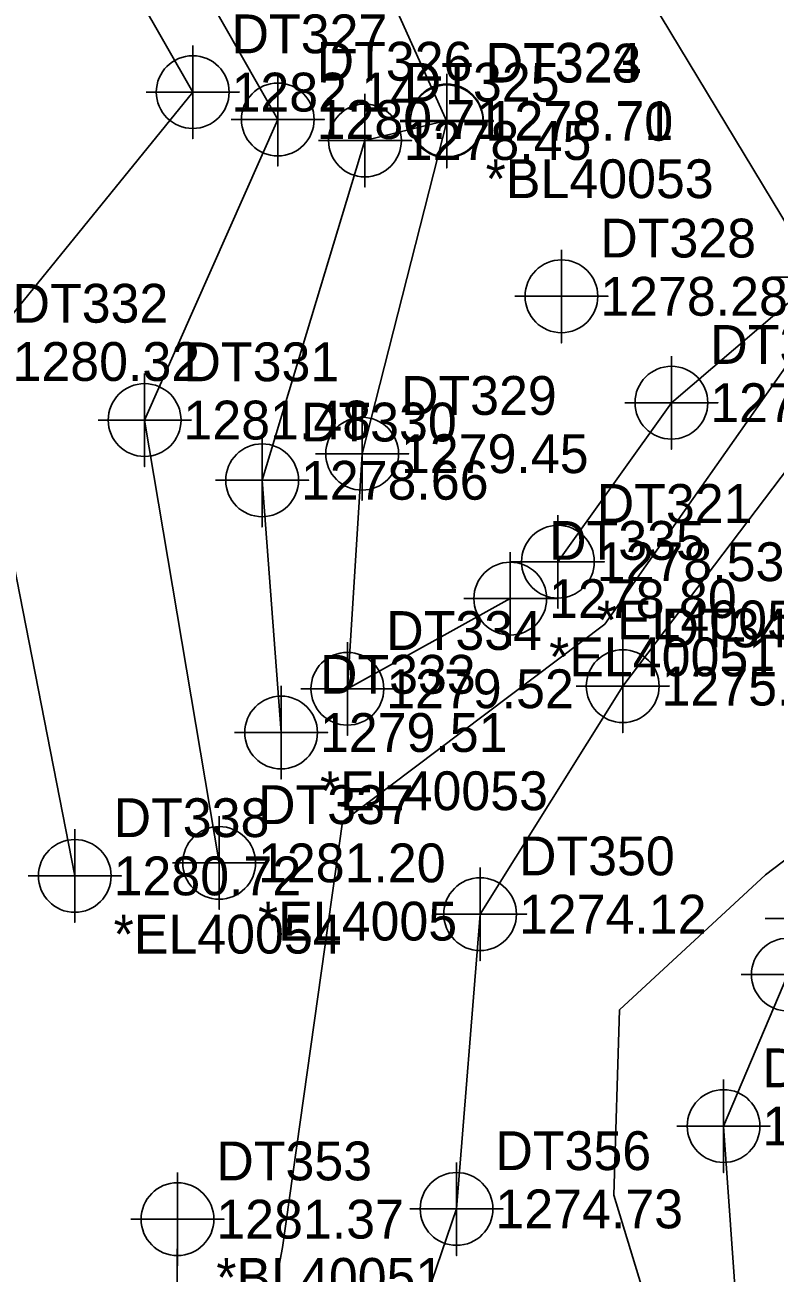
# Model space of a CAD drawing. Extents: x 1394009 to 1394411, y 957864 to 958364.
# Drawn here: x 1394139.9 to 1394188.2, y 958034.4 to 958114.8 of the extents above; entities that cross this region are included whole.
import ezdxf

# ---------------------------------------------------------------- set-up
doc = ezdxf.new("R2010")
doc.units = 0
for name, color, linetype in [('Exist DTM Breakline', 7, 'Continuous'), ('Exist DTM Breakline Cogo Comment', 7, 'Continuous'), ('Exist DTM Breakline Cogo Elevation', 7, 'Continuous'), ('Exist DTM Breakline Cogo Number', 7, 'Continuous'), ('Exist DTM Breakline Cogo Point CELL', 7, 'Continuous'), ('Exist DTM Breakline Underwater', 7, 'Continuous'), ('Exist DTM Breakline Underwater Cogo Elevation', 7, 'Continuous'), ('Exist DTM Breakline Underwater Cogo Number', 7, 'Continuous'), ('Exist DTM Breakline Underwater Cogo Point CELL', 7, 'Continuous'), ('Exist DTM Regular Point Cogo Elevation', 7, 'Continuous'), ('Exist Hydro Stream or Body of Water', 7, 'Continuous'), ('PH Exist DTM NCFMP LIDAR Elevation Point', 7, 'Continuous'), ('Raster_Level_0', 7, 'Continuous')]:
    doc.layers.add(name, color=color, linetype=linetype)

msp = doc.modelspace()

# ---------------------------------------------------------------- linework, layer by layer
at = {"layer": 'Exist DTM Breakline'}
for points in [[(1394070.1313, 958268.4251), (1394080.9574, 958242.6289), (1394101.6472, 958198.7507), (1394123.0372, 958162.9752), (1394143.223, 958131.4044), (1394156.1703, 958108.6674), (1394147.5951, 958089.3097), (1394152.395, 958060.7909)], [(1394078.4815, 958267.2528), (1394082.9126, 958267.3867), (1394095.8187, 958243.0525), (1394113.4272, 958206.3553), (1394134.4907, 958171.1858), (1394155.1759, 958139.8204), (1394165.1856, 958129.7757), (1394177.2665, 958121.2673), (1394190.9858, 958098.52), (1394181.5225, 958090.4285), (1394174.2125, 958080.1878)], [(1394065.3665, 958259.7005), (1394076.2432, 958241.6096), (1394098.862, 958196.9887), (1394119.1062, 958160.1529), (1394140.102, 958128.983), (1394150.6899, 958110.4316), (1394136.5853, 958093.0812), (1394143.0953, 958059.9522)], [(1394146.8464, 958135.0295), (1394160.4995, 958123.1391), (1394167.05, 958108.5477), (1394161.6029, 958087.1443)], [(1394166.7827, 958108.5345), (1394161.7854, 958107.3138), (1394155.1623, 958085.4306), (1394156.3852, 958069.1854)], [(1394161.6029, 958087.1443), (1394160.6523, 958072.0045), (1394171.1443, 958077.81)], [(1394205.7466, 958068.8917), (1394190.5711, 958057.2067), (1394189.0222, 958053.5957), (1394184.8806, 958043.8407), (1394186.4655, 958021.4355), (1394191.8774, 958003.2638), (1394213.2872, 957998.1706), (1394228.4733, 957975.4923), (1394239.8888, 957946.4968), (1394241.0497, 957903.4511)], [(1394149.71, 958037.8453), (1394149.558, 958011.2722), (1394170.1298, 957980.5225), (1394177.7403, 957975.0583), (1394196.6522, 957979.7455), (1394205.9408, 957961.0676), (1394214.1868, 957940.8417), (1394207.8738, 957917.8382)]]:
    msp.add_lwpolyline(points, dxfattribs=at)
at = {"layer": 'Exist DTM Breakline Cogo Point CELL'}
for points in [[(1394150.6899, 958113.4316), (1394150.6899, 958107.4316), (1394150.6899, 958110.4316), (1394153.6899, 958110.4316), (1394147.6899, 958110.4316)], [(1394156.1703, 958111.6674), (1394156.1703, 958105.6674), (1394156.1703, 958108.6674), (1394159.1703, 958108.6674), (1394153.1703, 958108.6674)], [(1394167.05, 958111.5477), (1394167.05, 958105.5477), (1394167.05, 958108.5477), (1394170.05, 958108.5477), (1394164.05, 958108.5477)], [(1394167.0579, 958111.6017), (1394167.0579, 958105.6017), (1394167.0579, 958108.6017), (1394170.0579, 958108.6017), (1394164.0579, 958108.6017)], [(1394161.7854, 958110.3138), (1394161.7854, 958104.3138), (1394161.7854, 958107.3138), (1394164.7854, 958107.3138), (1394158.7854, 958107.3138)], [(1394190.9858, 958101.52), (1394190.9858, 958095.52), (1394190.9858, 958098.52), (1394193.9858, 958098.52), (1394187.9858, 958098.52)], [(1394181.5225, 958093.4285), (1394181.5225, 958087.4285), (1394181.5225, 958090.4285), (1394184.5225, 958090.4285), (1394178.5225, 958090.4285)], [(1394147.5951, 958092.3097), (1394147.5951, 958086.3097), (1394147.5951, 958089.3097), (1394150.5951, 958089.3097), (1394144.5951, 958089.3097)], [(1394161.6029, 958090.1443), (1394161.6029, 958084.1443), (1394161.6029, 958087.1443), (1394164.6029, 958087.1443), (1394158.6029, 958087.1443)], [(1394155.1623, 958088.4306), (1394155.1623, 958082.4306), (1394155.1623, 958085.4306), (1394158.1623, 958085.4306), (1394152.1623, 958085.4306)], [(1394174.2125, 958083.1878), (1394174.2125, 958077.1878), (1394174.2125, 958080.1878), (1394177.2125, 958080.1878), (1394171.2125, 958080.1878)], [(1394171.1443, 958080.81), (1394171.1443, 958074.81), (1394171.1443, 958077.81), (1394174.1443, 958077.81), (1394168.1443, 958077.81)], [(1394160.6523, 958075.0045), (1394160.6523, 958069.0045), (1394160.6523, 958072.0045), (1394163.6523, 958072.0045), (1394157.6523, 958072.0045)], [(1394156.3852, 958072.1854), (1394156.3852, 958066.1854), (1394156.3852, 958069.1854), (1394159.3852, 958069.1854), (1394153.3852, 958069.1854)], [(1394152.395, 958063.7909), (1394152.395, 958057.7909), (1394152.395, 958060.7909), (1394155.395, 958060.7909), (1394149.395, 958060.7909)], [(1394143.0953, 958062.9522), (1394143.0953, 958056.9522), (1394143.0953, 958059.9522), (1394146.0953, 958059.9522), (1394140.0953, 958059.9522)], [(1394190.5711, 958060.2067), (1394190.5711, 958054.2067), (1394190.5711, 958057.2067), (1394193.5711, 958057.2067), (1394187.5711, 958057.2067)], [(1394189.0222, 958056.5957), (1394189.0222, 958050.5957), (1394189.0222, 958053.5957), (1394192.0222, 958053.5957), (1394186.0222, 958053.5957)], [(1394184.8806, 958046.8407), (1394184.8806, 958040.8407), (1394184.8806, 958043.8407), (1394187.8806, 958043.8407), (1394181.8806, 958043.8407)], [(1394149.71, 958040.8453), (1394149.71, 958034.8453), (1394149.71, 958037.8453), (1394152.71, 958037.8453), (1394146.71, 958037.8453)]]:
    msp.add_lwpolyline(points, dxfattribs=at)
for centre in [(1394150.6899, 958110.4316), (1394156.1703, 958108.6674), (1394167.05, 958108.5477), (1394167.0579, 958108.6017), (1394161.7854, 958107.3138), (1394181.5225, 958090.4285), (1394147.5951, 958089.3097), (1394161.6029, 958087.1443), (1394155.1623, 958085.4306), (1394174.2125, 958080.1878), (1394171.1443, 958077.81), (1394160.6523, 958072.0045), (1394156.3852, 958069.1854), (1394152.395, 958060.7909), (1394143.0953, 958059.9522), (1394189.0222, 958053.5957), (1394184.8806, 958043.8407), (1394149.71, 958037.8453)]:
    msp.add_circle(centre, 2.344, dxfattribs=at)
at = {"layer": 'Exist DTM Breakline Underwater'}
msp.add_lwpolyline([(1394192.3583, 958090.5901), (1394178.3868, 958072.1738), (1394169.2021, 958057.4892), (1394167.6851, 958038.5052), (1394159.1429, 958013.4636), (1394180.3464, 957994.6406), (1394199.7643, 957985.953), (1394224.0434, 957972.821), (1394228.1265, 957943.556), (1394220.9394, 957914.628)], dxfattribs=at)
at = {"layer": 'Exist DTM Breakline Underwater Cogo Point CELL'}
for points in [[(1394178.3868, 958075.1738), (1394178.3868, 958069.1738), (1394178.3868, 958072.1738), (1394181.3868, 958072.1738), (1394175.3868, 958072.1738)], [(1394169.2021, 958060.4892), (1394169.2021, 958054.4892), (1394169.2021, 958057.4892), (1394172.2021, 958057.4892), (1394166.2021, 958057.4892)], [(1394167.6851, 958041.5052), (1394167.6851, 958035.5052), (1394167.6851, 958038.5052), (1394170.6851, 958038.5052), (1394164.6851, 958038.5052)]]:
    msp.add_lwpolyline(points, dxfattribs=at)
for centre in [(1394178.3868, 958072.1738), (1394169.2021, 958057.4892), (1394167.6851, 958038.5052)]:
    msp.add_circle(centre, 2.344, dxfattribs=at)
at = {"layer": 'Exist Hydro Stream or Body of Water'}
for points in [[(1394190.7058, 958095.3239), (1394177.2279, 958076.1665), (1394160.3309, 958063.4331), (1394156.4808, 958036.0172), (1394151.8807, 958011.6814), (1394172.2345, 957982.059), (1394181.0188, 957978.4843), (1394196.9657, 957983.1686), (1394210.7106, 957964.4319), (1394215.4703, 957941.598), (1394209.5541, 957917.1532)], [(1394203.9517, 958072.4517), (1394187.582, 958060.0115), (1394178.1893, 958051.3287), (1394177.8231, 958039.3974), (1394183.6296, 958020.3053), (1394189.4903, 958000.9486), (1394211.9273, 957995.783), (1394226.7784, 957973.5412), (1394236.5763, 957945.2073), (1394231.9355, 957908.562)]]:
    msp.add_lwpolyline(points, dxfattribs=at)
at = {"layer": 'PH Exist DTM NCFMP LIDAR Elevation Point'}
msp.add_lwpolyline([(1394174.4403, 958100.2797), (1394174.4403, 958094.2797), (1394174.4403, 958097.2797), (1394177.4403, 958097.2797), (1394171.4403, 958097.2797)], dxfattribs=at)
msp.add_circle((1394174.4403, 958097.2797), 2.344, dxfattribs=at)

# ---------------------------------------------------------------- texts
at = {"layer": 'Exist DTM Breakline Cogo Comment'}
for s, p in [('*BL40053', (1394169.5579, 958103.6017)), ('*EL40053', (1394176.7125, 958075.1878)), ('*EL40051', (1394173.6443, 958072.81)), ('*EL40053', (1394158.8852, 958064.1854)), ('*EL4005', (1394154.895, 958055.7909)), ('*EL40054', (1394145.5953, 958054.9522)), ('*BL40051', (1394152.21, 958032.8453))]:
    msp.add_text(s, height=2.5, dxfattribs=at).set_placement(p)
at = {"layer": 'Exist DTM Breakline Cogo Elevation'}
for s, p in [('1282.14', (1394153.1899, 958109.1816)), ('1280.71', (1394158.6703, 958107.4174)), ('1278.70', (1394169.55, 958107.2977)), ('1278.71', (1394169.5579, 958107.3517)), ('1278.45', (1394164.2854, 958106.0638)), ('1280.32', (1394139.0853, 958091.8312)), ('1279.19', (1394184.0225, 958089.1785)), ('1281.48', (1394150.0951, 958088.0597)), ('1279.45', (1394164.1029, 958085.8943)), ('1278.66', (1394157.6623, 958084.1806)), ('1278.53', (1394176.7125, 958078.9378)), ('1278.80', (1394173.6443, 958076.56)), ('1279.52', (1394163.1523, 958070.7545)), ('1279.51', (1394158.8852, 958067.9354)), ('1281.20', (1394154.895, 958059.5409)), ('1280.72', (1394145.5953, 958058.7022)), ('1280.53', (1394187.3806, 958042.5907)), ('1281.37', (1394152.21, 958036.5953))]:
    msp.add_text(s, height=2.5, dxfattribs=at).set_placement(p)
at = {"layer": 'Exist DTM Breakline Cogo Number'}
for s, p in [('DT327', (1394153.1899, 958112.9316)), ('DT326', (1394158.6703, 958111.1674)), ('DT324', (1394169.5579, 958111.1017)), ('DT323', (1394169.55, 958111.0477)), ('DT325', (1394164.2854, 958109.8138)), ('DT332', (1394139.0853, 958095.5812)), ('DT320', (1394184.0225, 958092.9285)), ('DT331', (1394150.0951, 958091.8097)), ('DT329', (1394164.1029, 958089.6443)), ('DT330', (1394157.6623, 958087.9306)), ('DT321', (1394176.7125, 958082.6878)), ('DT335', (1394173.6443, 958080.31)), ('DT334', (1394163.1523, 958074.5045)), ('DT333', (1394158.8852, 958071.6854)), ('DT337', (1394154.895, 958063.2909)), ('DT338', (1394145.5953, 958062.4522)), ('DT348', (1394187.3806, 958046.3407)), ('DT353', (1394152.21, 958040.3453))]:
    msp.add_text(s, height=2.5, dxfattribs=at).set_placement(p)
at = {"layer": 'Exist DTM Breakline Underwater Cogo Elevation'}
for s, p in [('1275.68', (1394180.8868, 958070.9238)), ('1274.12', (1394171.7021, 958056.2392)), ('1274.73', (1394170.1851, 958037.2552))]:
    msp.add_text(s, height=2.5, dxfattribs=at).set_placement(p)
at = {"layer": 'Exist DTM Breakline Underwater Cogo Number'}
for s, p in [('DT344', (1394180.8868, 958074.6738)), ('DT350', (1394171.7021, 958059.9892)), ('DT356', (1394170.1851, 958041.0052))]:
    msp.add_text(s, height=2.5, dxfattribs=at).set_placement(p)
at = {"layer": 'Exist DTM Regular Point Cogo Elevation'}
msp.add_text('1278.28', height=2.5, dxfattribs=at).set_placement((1394176.9403, 958096.0297))
at = {"layer": 'Raster_Level_0'}
msp.add_text('DT328', height=2.5, dxfattribs=at).set_placement((1394176.9403, 958099.7797))

doc.saveas('drawing.dxf')
